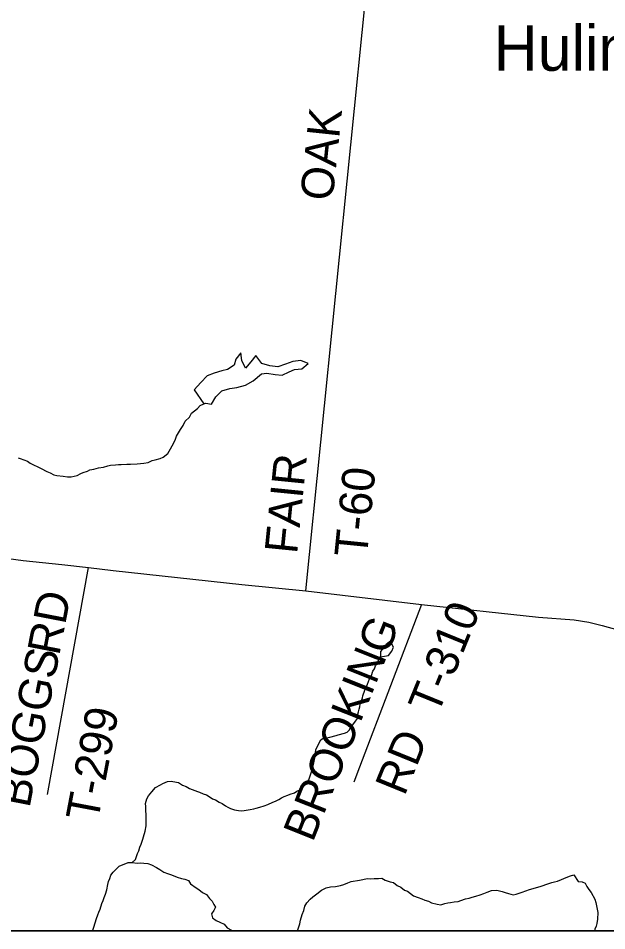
# Model space of a CAD drawing. Extents: x 0 to 39.3, y -3.9 to 22.
# Drawn here: x 6.099 to 7.123, y 13.9 to 15.488 of the extents above; entities that cross this region are included whole.
import ezdxf

# ---------------------------------------------------------------- set-up
doc = ezdxf.new("R2010")
doc.units = 0
for name, color, linetype in [('GM_X_Corporation', 7, 'Continuous'), ('GM_X_County_Road', 7, 'Continuous'), ('GM_X_Minor_Lake', 7, 'Continuous'), ('GM_X_Minor_River', 7, 'Continuous'), ('GM_X_Township_Road', 7, 'Continuous'), ('GM_X_Township_Road_Text', 7, 'Continuous'), ('GM_X_Unincorporated_Text', 7, 'Continuous'), ('SH_Data', 7, 'Continuous')]:
    doc.layers.add(name, color=color, linetype=linetype)

msp = doc.modelspace()

# ---------------------------------------------------------------- linework, layer by layer
at = {"layer": 'GM_X_Corporation'}
msp.add_lwpolyline([(3.8692, 13.9), (7.894, 13.9), (7.8685, 14.2638), (7.8533, 14.4986), (7.8368, 14.7531), (7.7467, 16.0631)], dxfattribs=at)
at = {"layer": 'GM_X_County_Road'}
msp.add_lwpolyline([(6.0819, 14.5477), (6.1075, 14.544), (6.1751, 14.5372), (6.2211, 14.532), (6.2642, 14.5267), (6.488, 14.5027), (6.5996, 14.4912), (6.8005, 14.4678), (7.0043, 14.4459), (7.0661, 14.4409), (7.0915, 14.4369), (7.1149, 14.4309), (7.1423, 14.4234), (7.1872, 14.4095), (7.2156, 14.4005), (7.2365, 14.393), (7.2555, 14.3831), (7.2799, 14.3681), (7.3458, 14.3278)], dxfattribs=at)
at = {"layer": 'GM_X_Minor_Lake'}
for points in [[(6.4222, 14.8167), (6.4255, 14.8178), (6.4353, 14.8161), (6.4431, 14.8289), (6.4535, 14.8397), (6.4669, 14.8433), (6.4791, 14.845), (6.4943, 14.8493), (6.5077, 14.8566), (6.522, 14.8689), (6.5315, 14.8703), (6.5459, 14.8681), (6.5584, 14.8668), (6.5703, 14.8727), (6.5798, 14.8767), (6.5924, 14.8776), (6.6032, 14.8869), (6.5907, 14.8924), (6.5766, 14.8908), (6.564, 14.8861), (6.5507, 14.881), (6.537, 14.8831), (6.5231, 14.8872), (6.5123, 14.901), (6.5037, 14.8898), (6.4945, 14.8789), (6.4878, 14.892), (6.4866, 14.9057), (6.4776, 14.8944), (6.4748, 14.8842), (6.4629, 14.8768), (6.453, 14.8743), (6.44, 14.87), (6.4278, 14.8657), (6.4166, 14.8537), (6.4054, 14.8413)], [(6.4054, 14.8413), (6.4222, 14.8167)]]:
    msp.add_lwpolyline(points, dxfattribs=at)
at = {"layer": 'GM_X_Minor_River'}
for points in [[(6.0989, 14.7226), (6.1027, 14.7217), (6.1152, 14.7173), (6.1197, 14.7138), (6.1389, 14.7044), (6.1491, 14.6989), (6.1544, 14.6965), (6.1608, 14.6933), (6.1661, 14.6921), (6.1771, 14.6908), (6.1851, 14.6899), (6.1912, 14.6901), (6.2015, 14.6919), (6.208, 14.6956), (6.2123, 14.6974), (6.2195, 14.6995), (6.2234, 14.7018), (6.2306, 14.7032), (6.2345, 14.7046), (6.2387, 14.7053), (6.2474, 14.7067), (6.2547, 14.7092), (6.2597, 14.7099), (6.2681, 14.7109), (6.2734, 14.7112), (6.278, 14.7115), (6.2879, 14.7117), (6.2943, 14.7116), (6.3062, 14.7125), (6.3176, 14.7138), (6.3249, 14.7149), (6.3318, 14.7182), (6.3371, 14.7196), (6.3459, 14.7217), (6.3513, 14.7243), (6.3594, 14.7302), (6.3614, 14.7344), (6.3692, 14.7476), (6.3728, 14.7555), (6.3744, 14.7608), (6.3815, 14.7721), (6.3862, 14.7793), (6.3897, 14.7864), (6.3971, 14.7935), (6.4003, 14.8007), (6.4111, 14.8089), (6.4153, 14.8138), (6.4222, 14.8167)], [(6.7291, 14.3767), (6.7432, 14.3788), (6.7487, 14.3863), (6.7518, 14.3935), (6.7478, 14.4008), (6.7448, 14.4027), (6.739, 14.3979)], [(6.739, 14.3979), (6.7355, 14.3938), (6.7324, 14.3896), (6.7293, 14.3859), (6.7291, 14.3767)], [(6.7136, 14.3439), (6.7161, 14.3515), (6.7188, 14.356), (6.7208, 14.3609), (6.724, 14.3666), (6.7263, 14.3722), (6.7291, 14.3767)], [(6.2974, 14.0189), (6.3032, 14.0241), (6.3068, 14.0347), (6.3088, 14.0392), (6.3108, 14.0452), (6.3132, 14.0509), (6.316, 14.0592), (6.3173, 14.0634), (6.3201, 14.0732), (6.3214, 14.0824), (6.3219, 14.0873), (6.3216, 14.0926), (6.3217, 14.0991), (6.3214, 14.1029), (6.3211, 14.1079), (6.3208, 14.1121), (6.3209, 14.1162), (6.3206, 14.1212), (6.3214, 14.1254), (6.3226, 14.1295), (6.3258, 14.1348), (6.3316, 14.1419), (6.3378, 14.1491), (6.3463, 14.1539), (6.3509, 14.1564), (6.359, 14.1597), (6.3651, 14.1604), (6.3742, 14.1587), (6.378, 14.1579), (6.3851, 14.1536), (6.3912, 14.1512), (6.3972, 14.1476), (6.4017, 14.1457), (6.4108, 14.1425), (6.4146, 14.1409), (6.421, 14.1381), (6.4267, 14.1365), (6.4312, 14.1334), (6.4372, 14.1298), (6.4421, 14.1278), (6.4485, 14.1235), (6.4538, 14.1216), (6.4598, 14.1176), (6.4636, 14.1149), (6.4685, 14.1125), (6.4753, 14.1105), (6.4821, 14.1093), (6.4871, 14.1088), (6.4924, 14.1091), (6.5024, 14.1108), (6.5092, 14.1122), (6.5131, 14.1133), (6.5196, 14.1151), (6.5268, 14.1172), (6.5333, 14.1198), (6.5418, 14.1235), (6.5464, 14.1253), (6.5522, 14.1282), (6.5568, 14.1312), (6.5618, 14.1334), (6.5679, 14.1359), (6.5721, 14.1374), (6.5794, 14.1399), (6.584, 14.1429), (6.5905, 14.1458), (6.5952, 14.1511), (6.6018, 14.1586), (6.6045, 14.1627), (6.6082, 14.1729), (6.6106, 14.1801), (6.6114, 14.1843), (6.6139, 14.1953), (6.6156, 14.2032), (6.616, 14.2093), (6.6169, 14.215), (6.6213, 14.2248), (6.6252, 14.2324), (6.6295, 14.235), (6.6356, 14.2356), (6.6409, 14.2367), (6.652, 14.2395), (6.6558, 14.241), (6.6669, 14.2438), (6.6711, 14.2453), (6.6746, 14.249), (6.677, 14.2528), (6.6813, 14.2581), (6.6856, 14.2648), (6.6891, 14.2693), (6.69, 14.2769), (6.6912, 14.2807), (6.692, 14.2853), (6.6933, 14.2898), (6.6941, 14.2944), (6.6965, 14.3), (6.6981, 14.305), (6.6985, 14.3088), (6.7021, 14.3186), (6.7065, 14.3288), (6.7101, 14.3386), (6.7136, 14.3439)], [(6.2282, 13.9), (6.2287, 13.9008), (6.2307, 13.9064), (6.2331, 13.914), (6.2351, 13.9212), (6.2375, 13.9276), (6.2395, 13.9325), (6.2415, 13.9378), (6.2443, 13.9472), (6.247, 13.9529), (6.2486, 13.9578), (6.251, 13.9639), (6.253, 13.9714), (6.2547, 13.9805), (6.2559, 13.9858), (6.2583, 13.9911), (6.2603, 13.9968), (6.2642, 14.002), (6.2699, 14.008), (6.2749, 14.0121), (6.2906, 14.019), (6.2974, 14.0189), (6.3061, 14.0176), (6.3122, 14.0179), (6.3175, 14.0178), (6.3247, 14.0169), (6.3311, 14.0145), (6.3397, 14.0098), (6.3457, 14.0067), (6.3525, 14.002), (6.3585, 13.9996), (6.3657, 13.9972), (6.3758, 13.9933), (6.383, 13.9912), (6.389, 13.9896), (6.3951, 13.9876), (6.3988, 13.9818), (6.4085, 13.9745), (6.4134, 13.9717), (6.4197, 13.9667), (6.4265, 13.9628), (6.4321, 13.9562), (6.4362, 13.9512), (6.4395, 13.9458), (6.4421, 13.9408), (6.4393, 13.9352), (6.4354, 13.9295), (6.4372, 13.9227), (6.4436, 13.9176), (6.45, 13.9149), (6.4571, 13.9117), (6.4627, 13.9048), (6.4702, 13.9008), (6.4759, 13.9004), (6.4768, 13.9)], [(6.585, 13.9), (6.5851, 13.9), (6.5867, 13.9053), (6.589, 13.9121), (6.5903, 13.9182), (6.5931, 13.9284), (6.5959, 13.9355), (6.5979, 13.9427), (6.6014, 13.9487), (6.6068, 13.9551), (6.6118, 13.9592), (6.6184, 13.9644), (6.6264, 13.9707), (6.6348, 13.9744), (6.6421, 13.9762), (6.6508, 13.9768), (6.6595, 13.9789), (6.6653, 13.9807), (6.6725, 13.9836), (6.6782, 13.9858), (6.6927, 13.9878), (6.6984, 13.9889), (6.706, 13.9907), (6.7113, 13.9902), (6.7181, 13.9908), (6.7257, 13.9911), (6.7314, 13.9914), (6.7374, 13.9882), (6.7461, 13.985), (6.7521, 13.9842), (6.7585, 13.9787), (6.7645, 13.9756), (6.7709, 13.9709), (6.7761, 13.9686), (6.7866, 13.9608), (6.7949, 13.958), (6.8013, 13.9556), (6.8062, 13.9532), (6.8126, 13.9512), (6.8179, 13.9488), (6.8281, 13.946), (6.8341, 13.9452), (6.8414, 13.9473), (6.8463, 13.9484), (6.8512, 13.949), (6.8573, 13.9501), (6.8642, 13.9511), (6.8691, 13.9525), (6.8771, 13.9554), (6.8836, 13.9568), (6.8889, 13.9583), (6.895, 13.9601), (6.9026, 13.9626), (6.9091, 13.9648), (6.9149, 13.9673), (6.9221, 13.9702), (6.9316, 13.9705), (6.9407, 13.9684), (6.9459, 13.9668), (6.952, 13.9648), (6.9603, 13.9624), (6.9652, 13.9634), (6.9755, 13.9674), (6.9885, 13.9718), (7.0071, 13.9772), (7.0121, 13.979), (7.0171, 13.9804), (7.027, 13.984), (7.0319, 13.9851), (7.0369, 13.9865), (7.0441, 13.9894), (7.0525, 13.9927), (7.0598, 13.9953), (7.0655, 13.9974), (7.0733, 13.9859), (7.0801, 13.985), (7.085, 13.983), (7.0879, 13.9769), (7.0916, 13.9715), (7.0957, 13.9665), (7.1019, 13.955), (7.1041, 13.9489), (7.1048, 13.9432), (7.1062, 13.9378), (7.1072, 13.9317), (7.107, 13.92), (7.1054, 13.9128), (7.1042, 13.9079), (7.1022, 13.9026), (7.1017, 13.9)]]:
    msp.add_lwpolyline(points, dxfattribs=at)
at = {"layer": 'GM_X_Township_Road'}
for p, q in [((6.1503, 14.1372), (6.2211, 14.532)), ((6.8005, 14.4678), (6.6925, 14.1844)), ((6.6925, 14.1844), (6.6826, 14.1586))]:
    msp.add_line(p, q, dxfattribs=at)
msp.add_lwpolyline([(6.5996, 14.4912), (6.7035, 15.5268), (6.7077, 15.5659), (6.7103, 15.5876), (6.7116, 15.6022), (6.7108, 15.6105), (6.7059, 15.6251), (6.7001, 15.6366), (6.6999, 15.6452), (6.7056, 15.6903), (6.714, 15.7659), (6.7205, 15.8216), (6.7215, 15.8394), (6.722, 15.8649), (6.7205, 15.9178), (6.7205, 15.9507), (6.7203, 15.976)], dxfattribs=at)
at = {"layer": 'SH_Data'}
msp.add_lwpolyline([(1.9, 21.1), (9.1, 21.1), (9.1, 13.9), (1.9, 13.9)], close=True, dxfattribs=at)

# ---------------------------------------------------------------- texts
at = {"layer": 'GM_X_Township_Road_Text'}
for s, rotation, p in [('OAK', 83.9909, (6.6458, 15.1687)), ('FAIR', 84.2591, (6.5841, 14.5545)), ('T-60', 84.3237, (6.7054, 14.5483)), ('RD', 79.0775, (6.1703, 14.3773)), ('T-310', 67.8338, (6.8286, 14.2734)), ('BROOKING', 68.2715, (6.6113, 14.0525)), ('BOGGS', 78.9686, (6.1186, 14.1123)), ('T-299', 79.2425, (6.2374, 14.088)), ('RD', 67.8342, (6.771, 14.1329))]:
    msp.add_text(s, height=0.05682, rotation=rotation, dxfattribs=at).set_placement(p)
at = {"layer": 'GM_X_Unincorporated_Text'}
msp.add_text('Hulington', height=0.07898, rotation=0, dxfattribs=at).set_placement((6.9264, 15.3964))

doc.saveas('drawing.dxf')
